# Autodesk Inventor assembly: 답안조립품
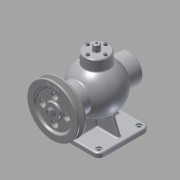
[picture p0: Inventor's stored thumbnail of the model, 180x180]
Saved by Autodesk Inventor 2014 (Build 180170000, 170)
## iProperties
Created: 2015-10
Part Number: 답안조립품
Document SubType Name: Assembly
Designer: youjin04
Author: youjin04
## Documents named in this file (19)
- C:\Users\youjin04\Desktop\451010V1014\답안조립품.iam
- C:\Users\youjin04\Desktop\451010V1014\본체.ipt
- C:\Users\youjin04\Desktop\451010V1014\뒤커버.ipt
- C:\Users\youjin04\Desktop\451010V1014\앞커버.ipt
- C:\Users\youjin04\Desktop\451010V1014\볼트 M4 x 16.ipt
- C:\Users\youjin04\Desktop\451010V1014\오일실 15 30 7.ipt
- C:\Users\youjin04\Desktop\451010V1014\베어링- 6202.ipt
- KS B 2023 - 6202 - 15 x 35 x 11 - 7.8.ipt
- C:\Users\youjin04\Desktop\451010V1014\편심축.ipt
- C:\Users\youjin04\Desktop\451010V1014\멈춤링- 35x1.6.ipt
- KS B 1336 - 35x1.6.ipt
- C:\Users\youjin04\Desktop\451010V1014\멈춤링- 15 x 1.ipt
- C:\Users\youjin04\Desktop\451010V1014\부시.ipt
- C:\Users\youjin04\Desktop\451010V1014\상부커버.ipt
- C:\Users\youjin04\Desktop\451010V1014\볼트 M 4 x 12.ipt
- C:\Users\youjin04\Desktop\451010V1014\키 4 x 4 x 12.ipt
- C:\Users\youjin04\Desktop\451010V1014\V-벨트풀리.ipt
- C:\Users\youjin04\Desktop\451010V1014\너트 M8.ipt
- C:\Users\youjin04\Desktop\451010V1014\슬라이드.ipt
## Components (16 placed, 5 different names)
1. KS B 2023 - 6202 - 15 x 35 x 11 - 7.8:1 — Mate:9, Mate:10, Angle:1
2. KS B 2023 - 6202 - 15 x 35 x 11 - 7.8:2 — Mate:11, Mate:12, Mate:13, Mate:14, Mate:15, Mate:16, Mate:17, Angle:2
3. KS B 1336 - 35x1.6:1 — Mate:13, Mate:14
4. V-벨트풀리:1 — Mate:28, Mate:29, Mate:30, Mate:31, Mate:32
5. ISO 4762 M4 x 16:1 — Insert:1
6. ISO 4762 M4 x 16:2
7. ISO 4762 M4 x 16:3
8. ISO 4762 M4 x 16:4
9. ISO 4762 M4 x 16:5 — Insert:2
10. ISO 4762 M4 x 16:6
11. ISO 4762 M4 x 16:7
12. ISO 4762 M4 x 16:8
13. KS B 1021 - 에 따름 ISO 1207 - 미터 A  M 4 x 12:1 — Insert:3
14. KS B 1021 - 에 따름 ISO 1207 - 미터 A  M 4 x 12:2
15. KS B 1021 - 에 따름 ISO 1207 - 미터 A  M 4 x 12:3
16. KS B 1021 - 에 따름 ISO 1207 - 미터 A  M 4 x 12:4
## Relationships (19: Mate 14, Insert 3, Angle 2)
- Insert:1: ISO 4762 M4 x 16:1
- Insert:2: ISO 4762 M4 x 16:5
- Mate:9: KS B 2023 - 6202 - 15 x 35 x 11 - 7.8:1
- Mate:10: KS B 2023 - 6202 - 15 x 35 x 11 - 7.8:1
- Mate:11: KS B 2023 - 6202 - 15 x 35 x 11 - 7.8:2
- Mate:12: KS B 2023 - 6202 - 15 x 35 x 11 - 7.8:2
- Mate:13: KS B 2023 - 6202 - 15 x 35 x 11 - 7.8:2 ↔ KS B 1336 - 35x1.6:1
- Mate:14: KS B 2023 - 6202 - 15 x 35 x 11 - 7.8:2 ↔ KS B 1336 - 35x1.6:1
- Mate:15: KS B 2023 - 6202 - 15 x 35 x 11 - 7.8:2
- Mate:16: KS B 2023 - 6202 - 15 x 35 x 11 - 7.8:2
- Mate:17: KS B 2023 - 6202 - 15 x 35 x 11 - 7.8:2
- Angle:1: KS B 2023 - 6202 - 15 x 35 x 11 - 7.8:1
- Angle:2: KS B 2023 - 6202 - 15 x 35 x 11 - 7.8:2
- Insert:3: KS B 1021 - 에 따름 ISO 1207 - 미터 A  M 4 x 12:1
- Mate:28: V-벨트풀리:1
- Mate:29: V-벨트풀리:1
- Mate:30: V-벨트풀리:1
- Mate:31: V-벨트풀리:1
- Mate:32: V-벨트풀리:1
